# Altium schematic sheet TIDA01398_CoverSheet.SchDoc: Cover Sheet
size 431 x 279 mm; Date: Not shown in title block; ApprovedBy: Not shown in title block; CheckedBy: Not shown in title block; Author: Not shown in title block; CompanyName: Not shown in title block; DrawnBy: Gustavo Martinez; Engineer: Not shown in title block; Organization: Not shown in title block; Address1: Not shown in title block; Address2: Not shown in title block; Address3: Not shown in title block; Address4: Not shown in title block; DocumentNumber: 1; Revision: Use project parameter SCH_Rev; SheetNumber: 1; SheetTotal: 4; PageSetup: Record=PageOptions¦CenterHorizontal=True¦CenterVertical=True¦PrintScale=0.64¦XCorrection=1.00¦YCorrection=1.00¦PrintKind=0¦BorderSize=5000000¦LeftOffset=0¦BottomOffset=0¦Orientation=2¦PaperLength=1000¦PaperWidth=1000¦Scale=100¦PaperSource=15¦PrintQuality=1200¦MediaType=1¦DitherType=10¦PrintScaleMode=1¦PaperKind=Letter¦PaperIndex=1
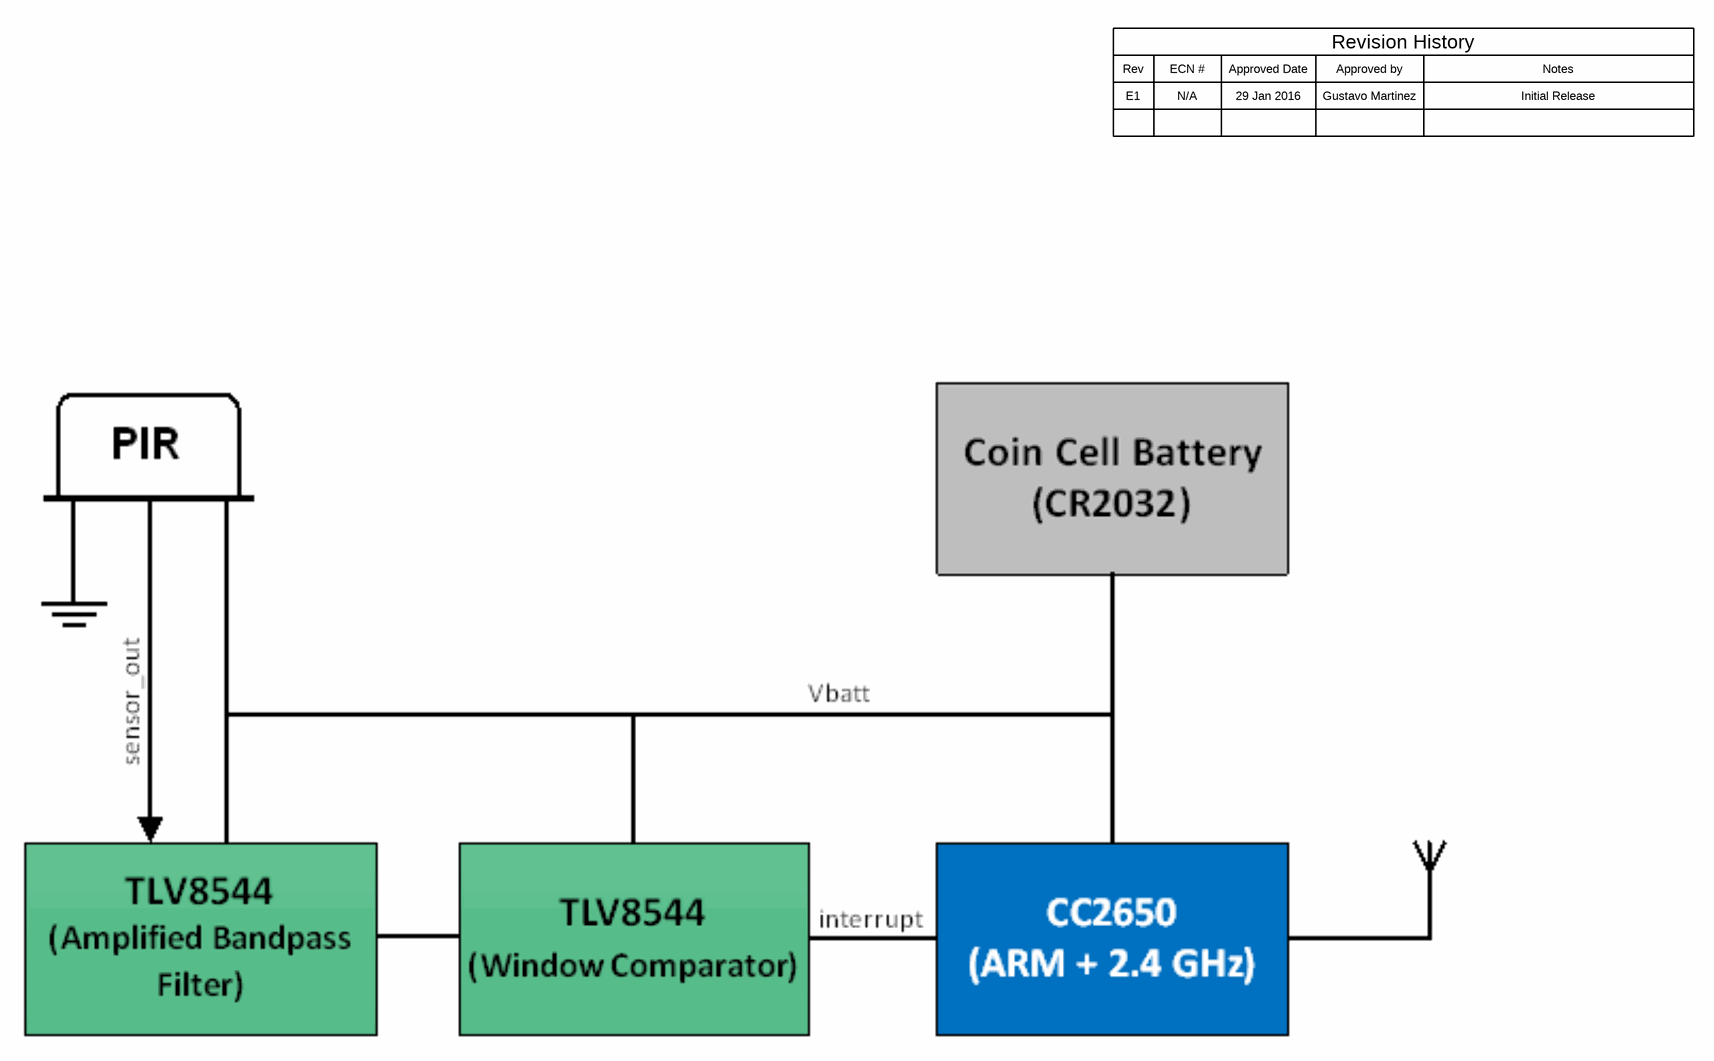
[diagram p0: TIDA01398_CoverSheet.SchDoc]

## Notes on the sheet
- Rev
- E1
- ECN #
- N/A
- Approved Date
- 29 Jan 2016
- Approved by
- Gustavo Martinez
- Revision History
- Notes
- Initial Release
